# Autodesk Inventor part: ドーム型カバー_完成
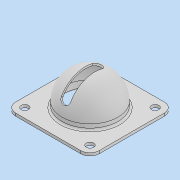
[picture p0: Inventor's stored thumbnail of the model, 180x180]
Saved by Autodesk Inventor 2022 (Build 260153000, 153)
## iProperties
Created: 2021-07
Part Number: ドーム型カバー_完成
Material: 一般
Document SubType Name: Modeling
Designer: DesignLab
Density: 1 g/cm^3
Appearance: 既定
Author: DesignLab
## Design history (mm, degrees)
sketch "スケッチ1"
  geometry: L1 (0, 0)-(30, 0); L2 (0, 0)-(30, 0); L3 (0, 0)-(0, 30); L4 (30, 0)-(30, -9); L5 (30, -9)-(0, -9); L6 (0, -9)-(0, 30); A1 r 30 centre (0, 0) between (30, 0) and (0, 30); 2 further points
  constraints: 12 end point, 2 point on circle, 2 vertical, 1 centre point, 1 coincident, 1 collinear, 1 horizontal, 1 perpendicular
  dimensions: "d0" = 30 radius of A1; "d1" = 0 distance between parallel lines of L1 L2; "d2" = 90 deg angle of L1 L3; "d3" = 9 distance of L2.end L4.end
revolve "回転1" sketch "スケッチ1" stored, may be unused: angle "d4" = 90 deg
feature "シェル1" dims "d5" = 2
sketch "スケッチ2"
  geometry: L1 (-39.913, 14.527)-(0, 0); L2 (0, 0)-(18.157, 38.938); L3 (-28, 0)-(28, 0) reference; A1 r 30 centre (0, 0) between (30, 0) and (-30, 0) reference; 2 further points
  constraints: 4 end point
  dimensions: "d6" = 95 deg angle of L2 L1; "d7" = 20 deg angle of L1 L3
extrude "押し出し1" cut sketch "スケッチ2" stored distance "d8" = 10; taper "d9" = 0 deg
feature "フルラウンド フィレット1"
feature "フルラウンド フィレット2"
sketch "スケッチ3"
  geometry: L1 (45, 45)-(-45, 45); L2 (-45, 45)-(-45, -45); L3 (-45, -45)-(45, -45); L4 (45, -45)-(45, 45); L5 (45, 45)-(-45, -45); L6 (-45, 45)-(45, -45); 1 further point
  constraints: 12 end point, 2 midpoint, 2 parallel, 1 horizontal, 1 perpendicular
  dimensions: "d10" = 90 distance of L3.end L2.end; "d11" = 90 distance of L2.end L1.end (= d10)
extrude "押し出し2" join sketch "スケッチ3" distance "d12" = 3; taper "d13" = 0 deg
feature "面を削除1"
sketch "スケッチ4"
  geometry: L1 (0, 0)-(90, 0) reference; L2 (90, 0)-(90, 90) reference; 2 further points
  dimensions: "d14" = 10 distance from line of L1 point (80, 10); "d15" = 10 distance from line of L2 point (80, 10)
hole "穴1" sketch "スケッチ4" at (80, 10) diameter "d16" = 8; stored, may be unused: countersink angle "d20" = 90 deg, drill point angle "d22" = 118 deg; dims "d17" = 6, "d18" = 4, "d19" = 2, "d21" = 8
fillet "フィレット1" dims "d23" = 10
mirror "ミラー1"
mirror "ミラー2"
fillet "フィレット2" dims "d24" = 2
node "ソリッド1"
